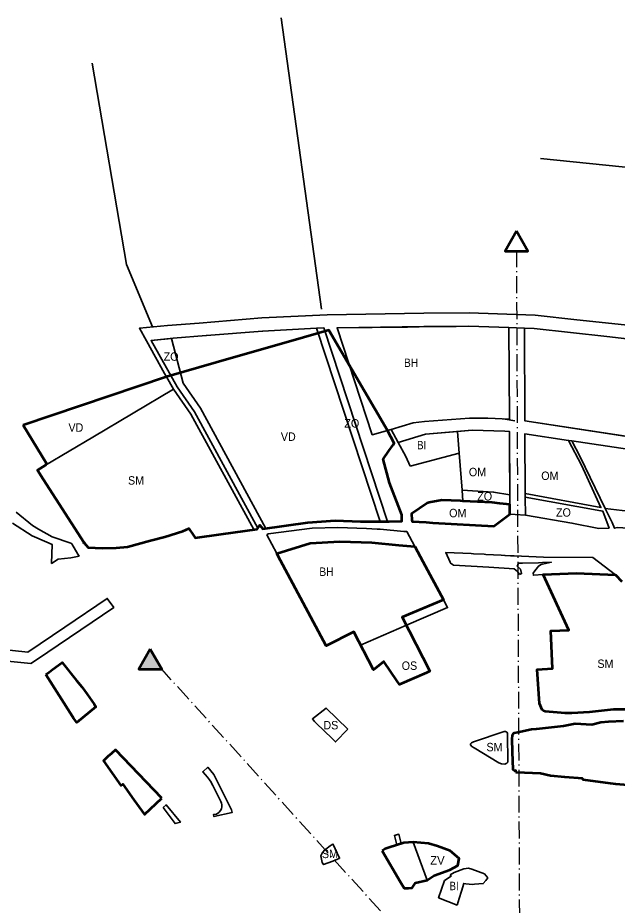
# Model space of a CAD drawing. Extents: x -650276 to -642489, y -1074311 to -1066658.
# Drawn here: x -647782 to -646929, y -1070373 to -1069110 of the extents above; entities that cross this region are included whole.
import ezdxf

# ---------------------------------------------------------------- set-up
doc = ezdxf.new("R2010")
doc.units = 0
doc.header["$LTSCALE"] = 4.8
doc.header["$PDMODE"] = 32
doc.header["$PDSIZE"] = 2.4
doc.linetypes.add('DOT_DASHED', pattern=[7.7, 5, -1.2, 0.3, -1.2])
for name, color, linetype, lineweight in [('1', 7, 'Continuous', 35), ('12', 7, 'Continuous', 35), ('15', 7, 'Continuous', 35), ('18', 7, 'Continuous', 35), ('2', 7, 'Continuous', 35), ('24', 7, 'Continuous', 35), ('35', 7, 'Continuous', 35), ('40', 7, 'Continuous', 35), ('42', 7, 'Continuous', 35), ('54', 7, 'Continuous', 35), ('55', 7, 'Continuous', 53), ('60', 7, 'Continuous', 53), ('9', 7, 'Continuous', 35)]:
    doc.layers.add(name, color=color, linetype=linetype, lineweight=lineweight)
doc.layers.add('62', color=7, linetype='Continuous')

msp = doc.modelspace()

# ---------------------------------------------------------------- hatches: boundary and pattern name
at = {"layer": '55'}
msp.add_hatch(color=256, dxfattribs=at).paths.add_polyline_path([(-647593.545, -1070008.59), (-647609.496, -1070037.236), (-647577.112, -1070037.236)])

# ---------------------------------------------------------------- linework, layer by layer
at = {"layer": '1'}
for points in [[(-647251.002, -1069695.852), (-647219.628, -1069686.746), (-647203.374, -1069684.716), (-647139.649, -1069679.961), (-647113.255, -1069679.966), (-647082.761, -1069681.399), (-647083.356, -1069551.018), (-647140.247, -1069549.071), (-647158.572, -1069549.252), (-647211.05, -1069549.77), (-647227.623, -1069550.23), (-647327.682, -1069551.263), (-647277.71, -1069703.421)], [(-646944.168, -1069563.743), (-647047.648, -1069552.245), (-647061.304, -1069551.773), (-647060.7, -1069683.894), (-646863, -1069714), (-646846, -1069575)], [(-647365.866, -1069857.774), (-647413.461, -1069872.442), (-647343.28, -1070003.81), (-647339.69, -1070001.95), (-647330.5, -1069997.19), (-647304.05, -1069983.79), (-647294.257, -1070002.745), (-647229.096, -1069974.658), (-647235, -1069963), (-647176.499, -1069938.333), (-647205.781, -1069883.796), (-647217.177, -1069862.57), (-647243.231, -1069860.34), (-647278.525, -1069857.002), (-647323.794, -1069855.468)]]:
    msp.add_lwpolyline(points, close=True, dxfattribs=at)
at = {"layer": '12'}
for points in [[(-647150.138, -1069782.334), (-647105.334, -1069785.168), (-647082.271, -1069788.81), (-647082.682, -1069698.791), (-647089.456, -1069698.579), (-647135.585, -1069697.137), (-647156.782, -1069698.901), (-647154.33, -1069729.69)], [(-647060.23, -1069786.932), (-646952.56, -1069807.13), (-646980.4, -1069746.98), (-646998.56, -1069711.443), (-647060.617, -1069702.116)]]:
    msp.add_lwpolyline(points, close=True, dxfattribs=at)
for points in [[(-647107.04, -1069799.84), (-647148.9, -1069797.88), (-647148.9, -1069797.88), (-647178.73, -1069796.4), (-647196.616, -1069800.068)], [(-647196.616, -1069800.068), (-647199.65, -1069800.69), (-647221.87, -1069816.21), (-647221.28, -1069824.74), (-647221.14, -1069826.761), (-647191.66, -1069828.58), (-647201.106, -1069827.997), (-647191.66, -1069828.58), (-647104.741, -1069833.568)], [(-647082.206, -1069802.916), (-647107.04, -1069799.84), (-647107.04, -1069799.84)], [(-647104.741, -1069833.568), (-647082.145, -1069816.321), (-647082.206, -1069802.916)]]:
    msp.add_lwpolyline(points, dxfattribs=at)
at = {"layer": '15'}
for points in [[(-646910.029, -1069548.006), (-646986.633, -1069539.757), (-647046.325, -1069533.275), (-647140.008, -1069530.068), (-647204.293, -1069530.647), (-647341.697, -1069532.602), (-647434.969, -1069537.141), (-647523.931, -1069544.499), (-647568.792, -1069548.21), (-647608.81, -1069551.868), (-647598.735, -1069570.026), (-647573.15, -1069616.16), (-647570.37, -1069621.18), (-647560.36, -1069638.39), (-647535.588, -1069674.163), (-647446.322, -1069838.338), (-647441.19, -1069837.6), (-647440.46, -1069836.558), (-647530.471, -1069671.013), (-647555.266, -1069635.207), (-647592.199, -1069569.411), (-647560.836, -1069566.036), (-647514.067, -1069562.282), (-647513.66, -1069562.249), (-647433.779, -1069556.106), (-647433.779, -1069556.106), (-647356.899, -1069552.034), (-647346.554, -1069551.486), (-647256.034, -1069827.107), (-647235.49, -1069826.51), (-647235.62, -1069817.62), (-647253.45, -1069771.95), (-647262.46, -1069738.25), (-647259.11, -1069733.52), (-647253.97, -1069726.27), (-647246.42, -1069715.63), (-647249.555, -1069709.677), (-647256.061, -1069697.32), (-647277.71, -1069703.421), (-647327.682, -1069551.263), (-647204.208, -1069549.647), (-647140.247, -1069549.071), (-647083.356, -1069551.018), (-647061.304, -1069551.773), (-647047.702, -1069552.239), (-646944.167, -1069563.743), (-646822.169, -1069577.72)], [(-647083.356, -1069551.018), (-647082.761, -1069681.399), (-647113.255, -1069679.966), (-647139.649, -1069679.961), (-647203.374, -1069684.716), (-647219.628, -1069686.746), (-647251.002, -1069695.852), (-647240.994, -1069714.513), (-647202.181, -1069702.678), (-647135.585, -1069697.137), (-647089.456, -1069698.579), (-647082.682, -1069698.791), (-647082.145, -1069816.321)], [(-647060.617, -1069702.116), (-646998.56, -1069711.443), (-646993.771, -1069712.163), (-646775.286, -1069745.022), (-646734.48, -1069751.35), (-646732.143, -1069733.308), (-646772.906, -1069727.176), (-646842.148, -1069716.763), (-647060.7, -1069683.894), (-647061.304, -1069551.773), (-647083.356, -1069551.018)], [(-647082.145, -1069816.321), (-647082.145, -1069816.321), (-647074.72, -1069816.8), (-647060.029, -1069817.854), (-647060.206, -1069792.294), (-647060.23, -1069786.932), (-647060.617, -1069702.116)], [(-647082.206, -1069802.916), (-647107.04, -1069799.84), (-647148.9, -1069797.88), (-647148.9, -1069797.88), (-647178.73, -1069796.4), (-647196.616, -1069800.068)], [(-647196.616, -1069800.068), (-647199.65, -1069800.69), (-647221.87, -1069816.21), (-647221.28, -1069824.74), (-647221.14, -1069826.761), (-647205.603, -1069827.72), (-647191.66, -1069828.58), (-647201.106, -1069827.997), (-647191.66, -1069828.58), (-647104.741, -1069833.568)], [(-647104.741, -1069833.568), (-647082.145, -1069816.321), (-647082.206, -1069802.916)], [(-646931.67, -1069902.89), (-646964.111, -1069878.315), (-647034.195, -1069877.629), (-647076, -1069875.85), (-647081.25, -1069875.56), (-647081.26, -1069875.76), (-647088.94, -1069875.34), (-647088.93, -1069875.14), (-647094.24, -1069874.85), (-647116.31, -1069873.65), (-647118.77, -1069873.51), (-647133.58, -1069872.73), (-647136.94, -1069872.55), (-647173.23, -1069871.09), (-647167.14, -1069884.85)], [(-647167.14, -1069884.85), (-647166.8, -1069885.63), (-647163.55, -1069887.98), (-647162.03, -1069888.89), (-647111.76, -1069891.77)], [(-647068.2, -1069902.28), (-647065.47, -1069901.09), (-647067.02, -1069894.68), (-647071.73, -1069890.39), (-647070.87, -1069888.71), (-647069.57, -1069886.35), (-647064.32, -1069886.23), (-647041.25, -1069885.62), (-647035.6, -1069885.43), (-647023.04, -1069885), (-647035.53, -1069887.44), (-647037.79, -1069887.88), (-647041.47, -1069890.42), (-647042.75, -1069892.14), (-647046.49, -1069897.19), (-647048.8, -1069900.51), (-647048.67, -1069903.32), (-647034.51, -1069902.21)], [(-647111.76, -1069891.77), (-647075.97, -1069894.33), (-647071, -1069897.87), (-647068.2, -1069902.28)], [(-647034.51, -1069902.21), (-647032.16, -1069902.13), (-646987.56, -1069900.52), (-646931.67, -1069902.89)]]:
    msp.add_lwpolyline(points, dxfattribs=at)
for points in [[(-647217.177, -1069862.57), (-647228.77, -1069840.98), (-647232.66, -1069841.07), (-647266.62, -1069837.86), (-647270.71, -1069837.61), (-647285.9, -1069836.66), (-647326.71, -1069835.46), (-647363.21, -1069836.64), (-647425.73, -1069844.31), (-647427.62, -1069845.94), (-647413.461, -1069872.442), (-647365.866, -1069857.774), (-647323.794, -1069855.468), (-647278.525, -1069857.002), (-647239.912, -1069860.654)], [(-647815.788, -1070007.72), (-647767.622, -1070012.66), (-647714.989, -1069977.087), (-647654.577, -1069936.255), (-647645.274, -1069949.279), (-647755.356, -1070023.682), (-647763.476, -1070029.17), (-647820.515, -1070023.319), (-647818.81, -1070016.41)], [(-647235, -1069963), (-647176.499, -1069938.333), (-647170.546, -1069949.42), (-647229.096, -1069974.658)], [(-647493.13, -1070225.217), (-647492.138, -1070227.681), (-647491.692, -1070229.974), (-647491.767, -1070233.217), (-647492.286, -1070235.393), (-647493.254, -1070237.6), (-647495.889, -1070240.926), (-647499.448, -1070243.223), (-647503.6, -1070243.95), (-647502.82, -1070246.91), (-647476.94, -1070240.79), (-647477.78, -1070237.42), (-647484.35, -1070223.91), (-647491.97, -1070208.95), (-647499.68, -1070193.54), (-647502.99, -1070186.94), (-647511.73, -1070176.61), (-647518.813, -1070183.069), (-647512.222, -1070190.785), (-647509.223, -1070194.61), (-647507.054, -1070197.854), (-647505.688, -1070200.172), (-647504.419, -1070202.575)], [(-647575.15, -1070233.71), (-647570.887, -1070229.877), (-647550.603, -1070254.911), (-647558.19, -1070256.86)], [(-647575.15, -1070233.71), (-647558.19, -1070256.86), (-647550.603, -1070254.911), (-647570.887, -1070229.877)], [(-647242.698, -1070287.238), (-647236.567, -1070285.154), (-647239.781, -1070272.031), (-647242.06, -1070272.35), (-647246.28, -1070273.733)]]:
    msp.add_lwpolyline(points, close=True, dxfattribs=at)
at = {"layer": '18'}
for points in [[(-647560.36, -1069638.39), (-647674.901, -1069706.701), (-647742.36, -1069746.93)], [(-647446.322, -1069838.338), (-647535.588, -1069674.163), (-647560.36, -1069638.39)], [(-647742.36, -1069746.93), (-647752.32, -1069752.95), (-647753.7, -1069753.9)], [(-647753.7, -1069753.9), (-647751.66, -1069757.12), (-647745.84, -1069766.71), (-647737.17, -1069780.85), (-647700.58, -1069837.2), (-647687.45, -1069857.15), (-647681.51, -1069863.72)], [(-647641.78, -1069864.26), (-647625.83, -1069863.19), (-647593.07, -1069853.74), (-647583.62, -1069851.13), (-647572.63, -1069848.63), (-647559.47, -1069844.92), (-647547.12, -1069840.87), (-647538.34, -1069836.68), (-647536.82, -1069838.87), (-647531.33, -1069847.23), (-647529.5, -1069849.99), (-647500.03, -1069846.28), (-647492.76, -1069845.02), (-647446.322, -1069838.338)], [(-647681.51, -1069863.72), (-647661.79, -1069864.92), (-647641.78, -1069864.26)], [(-646922.79, -1069912.31), (-646931.67, -1069902.89), (-646987.56, -1069900.52), (-647032.16, -1069902.13), (-647034.51, -1069902.21), (-646998.06, -1069981.49), (-647024.05, -1069982.48), (-647021.27, -1070036.28), (-647043.25, -1070037.29), (-647040.12, -1070086.11), (-647036.03, -1070094.96), (-647034.17, -1070096.49), (-647031.73, -1070097.21), (-647003.49, -1070099.66), (-646993.92, -1070099.49), (-646968.89, -1070098.02), (-646934.63, -1070094.24), (-646904.97, -1070094.52)]]:
    msp.add_lwpolyline(points, dxfattribs=at)
for points in [[(-646785.437, -1069827.534), (-646775.286, -1069745.022), (-646993.771, -1069712.163), (-646981.92, -1069734.86), (-646946.369, -1069808.291)], [(-647097.63, -1070170.37), (-647093.89, -1070171.55), (-647089.47, -1070172.21), (-647086.62, -1070170.89), (-647084.98, -1070169.29), (-647085.17, -1070154.78), (-647085.24, -1070144.07), (-647085.62, -1070128.24), (-647086.49, -1070126.62), (-647088.08, -1070125.63), (-647090.2, -1070125.64), (-647133.96, -1070140.44), (-647136.65, -1070141.75), (-647137.99, -1070143.09), (-647137.96, -1070144.66), (-647136.09, -1070146.97), (-647132.95, -1070149.08)], [(-647333.87, -1070285.66), (-647324.11, -1070306.21), (-647324.94, -1070306.63), (-647327.18, -1070307.52), (-647333.97, -1070310.22), (-647346.97, -1070315.05), (-647349, -1070312), (-647350.67, -1070302.55), (-647348.677, -1070297.894), (-647345.27, -1070293.99), (-647343.9, -1070292.96), (-647337.56, -1070288.43), (-647334.91, -1070286.51)]]:
    msp.add_lwpolyline(points, close=True, dxfattribs=at)
msp.add_point((-647687.45, -1069857.15), dxfattribs=at)
at = {"layer": '2'}
msp.add_lwpolyline([(-647223.66, -1069748.26), (-647154.33, -1069729.69), (-647156.782, -1069698.901), (-647202.181, -1069702.678), (-647240.994, -1069714.513), (-647230.16, -1069734.42)], close=True, dxfattribs=at)
for points in [[(-647167.03, -1070329.81), (-647165.36, -1070331.59), (-647174.81, -1070338.01), (-647183.55, -1070362.35), (-647156.9, -1070372.69)], [(-647113.37, -1070333.96), (-647118.28, -1070328.29), (-647135.94, -1070321.54), (-647140.83, -1070320.47), (-647147.66, -1070321.04), (-647161.17, -1070326.29), (-647167.03, -1070329.81)], [(-647156.9, -1070372.69), (-647154.31, -1070363.46), (-647151.09, -1070353.15), (-647147.6, -1070341.95), (-647144.57, -1070342.42), (-647139.84, -1070343.16), (-647135.62, -1070343.32), (-647132.49, -1070342.91)], [(-647132.49, -1070342.91), (-647119.88, -1070342.1), (-647116.03, -1070337.68), (-647113.37, -1070333.96)]]:
    msp.add_lwpolyline(points, dxfattribs=at)
at = {"layer": '24'}
msp.add_lwpolyline([(-647312.485, -1070122.583), (-647329.932, -1070140.465), (-647334.81, -1070135.73), (-647357.4, -1070113.69), (-647359.8, -1070111.34), (-647362.87, -1070107.74), (-647343.454, -1070092.368)], close=True, dxfattribs=at)
at = {"layer": '35'}
for points in [[(-647356.899, -1069552.034), (-647433.779, -1069556.106), (-647433.779, -1069556.106), (-647513.66, -1069562.249), (-647514.067, -1069562.282), (-647560.836, -1069566.036), (-647563.104, -1069566.28)], [(-647369.3, -1069828.22), (-647330.46, -1069825.51), (-647294.38, -1069826.88), (-647270.09, -1069827.02), (-647266.581, -1069827.042), (-647356.899, -1069552.034)], [(-647563.104, -1069566.28), (-647546.777, -1069629.901), (-647521.943, -1069665.763)], [(-647521.943, -1069665.763), (-647428.993, -1069836.714), (-647369.3, -1069828.22)]]:
    msp.add_lwpolyline(points, dxfattribs=at)
msp.add_lwpolyline([(-647740.74, -1069744.24), (-647742.36, -1069746.93), (-647674.901, -1069706.701), (-647560.36, -1069638.39), (-647570.37, -1069621.18), (-647701.61, -1069665.279), (-647774.11, -1069689.64)], close=True, dxfattribs=at)
at = {"layer": '40'}
msp.add_lwpolyline([(-647199.79, -1070337.21), (-647189.63, -1070330.53), (-647167.43, -1070322.66), (-647155.89, -1070316.51), (-647154.23, -1070306.63), (-647167.15, -1070295.69), (-647184.77, -1070288.73), (-647197.68, -1070285.3), (-647219.36, -1070283.36)], close=True, dxfattribs=at)
at = {"layer": '42'}
msp.add_line((-647266.581, -1069827.042), (-647256.034, -1069827.107), dxfattribs=at)
for points in [[(-647256.034, -1069827.107), (-647346.554, -1069551.486), (-647356.899, -1069552.034), (-647266.581, -1069827.042)], [(-647082.271, -1069788.81), (-647105.334, -1069785.168), (-647105.334, -1069785.168), (-647150.138, -1069782.334), (-647148.9, -1069797.88), (-647107.04, -1069799.84)], [(-647107.04, -1069799.84), (-647082.206, -1069802.916), (-647082.271, -1069788.81)], [(-647789.55, -1069829.12), (-647761.54, -1069847.24), (-647740.46, -1069856.29), (-647733.06, -1069859.46), (-647733.71, -1069886.65), (-647724.35, -1069880.48), (-647706.39, -1069878.81), (-647694.63, -1069876.07), (-647696.25, -1069873.35), (-647704.99, -1069858.7), (-647706.44, -1069857.98), (-647732.93, -1069848.5), (-647752.25, -1069837.95), (-647760.79, -1069832.61), (-647783.96, -1069813.49)]]:
    msp.add_lwpolyline(points, dxfattribs=at)
for points in [[(-647555.266, -1069635.207), (-647530.471, -1069671.013), (-647440.46, -1069836.558), (-647437.46, -1069832.27), (-647433.32, -1069837.33), (-647428.993, -1069836.714), (-647521.943, -1069665.763), (-647546.777, -1069629.901), (-647563.104, -1069566.28), (-647592.199, -1069569.411)], [(-646775.286, -1069745.022), (-646785.437, -1069827.534), (-646946.369, -1069808.291), (-646936.6, -1069828.47), (-646933.39, -1069836.51), (-646929.67, -1069835.68), (-646826.63, -1069841.84), (-646778.74, -1069850.44), (-646751.8, -1069853.72), (-646743.31, -1069854.26), (-646743.7, -1069850.07), (-646745.56, -1069829.84), (-646743.85, -1069817.72), (-646734.48, -1069751.35)], [(-646993.81, -1069829.12), (-646993.81, -1069829.12), (-646955.45, -1069836.93), (-646940.94, -1069836.34), (-646950.08, -1069812.16), (-646952.68, -1069811.69), (-647060.206, -1069792.294), (-647060.029, -1069817.854)]]:
    msp.add_lwpolyline(points, close=True, dxfattribs=at)
at = {"layer": '54'}
for p, q in [((-647407.408, -1069110.064), (-647349.831, -1069524.717)), ((-646340.757, -1069381.428), (-647038.68, -1069310.312)), ((-647091.408, -1069680.918), (-647074.799, -1069683.763))]:
    msp.add_line(p, q, dxfattribs=at)
msp.add_lwpolyline([(-647675.801, -1069174.849), (-647627, -1069461), (-647590.168, -1069549.978)], dxfattribs=at)
at = {"layer": '55', "linetype": 'DOT_DASHED', "lineweight": 25}
for p, q in [((-647072.859, -1069440.93), (-647067.564, -1070600.224)), ((-647067.564, -1070600.224), (-647577.112, -1070037.236))]:
    msp.add_line(p, q, dxfattribs=at)
at = {"layer": '55'}
for points in [[(-647072.884, -1069413.607), (-647088.835, -1069442.253), (-647056.451, -1069442.253)], [(-647593.545, -1070008.59), (-647609.496, -1070037.236), (-647577.112, -1070037.236)]]:
    msp.add_lwpolyline(points, close=True, dxfattribs=at)
at = {"layer": '60'}
for points in [[(-647774.11, -1069689.64), (-647740.74, -1069744.24), (-647742.36, -1069746.93), (-647753.7, -1069753.9), (-647745.84, -1069766.71), (-647687.45, -1069857.15), (-647681.51, -1069863.72), (-647661.79, -1069864.92), (-647641.78, -1069864.26), (-647625.83, -1069863.19), (-647593.07, -1069853.74), (-647572.63, -1069848.63), (-647547.12, -1069840.87), (-647538.34, -1069836.68), (-647531.33, -1069847.23), (-647529.5, -1069849.99), (-647492.76, -1069845.02), (-647441.19, -1069837.6), (-647437.46, -1069832.27), (-647433.32, -1069837.33), (-647369.3, -1069828.22), (-647330.46, -1069825.51), (-647294.38, -1069826.88), (-647270.09, -1069827.02), (-647253.88, -1069827.12), (-647236.5, -1069826.63), (-647235.49, -1069826.51), (-647235.62, -1069817.62), (-647253.45, -1069771.95), (-647262.46, -1069738.25), (-647253.97, -1069726.27), (-647247.86, -1069717.66), (-647246.42, -1069715.63), (-647256.061, -1069697.32), (-647339.58, -1069554.46), (-647375.71, -1069564.91), (-647499.63, -1069600.73), (-647570.37, -1069621.18)], [(-647196.616, -1069800.068), (-647199.65, -1069800.69), (-647221.87, -1069816.21), (-647221.28, -1069824.74), (-647221.14, -1069826.761), (-647201.106, -1069827.997), (-647191.66, -1069828.58), (-647104.741, -1069833.568), (-647082.145, -1069816.321), (-647082.206, -1069802.916), (-647096.39, -1069801.15), (-647107.04, -1069799.84), (-647148.9, -1069797.88), (-647152.39, -1069797.7), (-647178.73, -1069796.4)], [(-647408.115, -1069882.449), (-647413.461, -1069872.442), (-647365.866, -1069857.774), (-647323.794, -1069855.468), (-647278.525, -1069857.002), (-647239.912, -1069860.654), (-647217.177, -1069862.57), (-647205.781, -1069883.796), (-647176.499, -1069938.333), (-647235, -1069963), (-647195.933, -1070040.107), (-647200.796, -1070042.246), (-647238.99, -1070059.05), (-647238.99, -1070059.05), (-647242.362, -1070054.067), (-647261.27, -1070026.12), (-647276, -1070038.08), (-647304.05, -1069983.79), (-647343.28, -1070003.81), (-647397.738, -1069901.873)], [(-647741.98, -1070044.74), (-647737.34, -1070041.32), (-647732.47, -1070037.73), (-647718.564, -1070027.479), (-647698.172, -1070052.962), (-647690.674, -1070062.331), (-647683.145, -1070072.735), (-647673.357, -1070086.635), (-647670.687, -1070090.426), (-647697.889, -1070112.941), (-647702.57, -1070106.56), (-647704.02, -1070104.5)], [(-647576.812, -1070220.636), (-647642.855, -1070151.617), (-647648.73, -1070157.05), (-647653.52, -1070161.48), (-647659.831, -1070167.317), (-647635.1, -1070202.5), (-647632.56, -1070200.72), (-647616.6, -1070223), (-647601.726, -1070243.764)], [(-647263.72, -1070295.43), (-647237.57, -1070340.12), (-647232.55, -1070348.65), (-647226.24, -1070348.88), (-647220.9, -1070348.04), (-647216.16, -1070340.99), (-647199.79, -1070337.21), (-647189.63, -1070330.53), (-647167.43, -1070322.66), (-647155.89, -1070316.51), (-647154.23, -1070306.63), (-647167.15, -1070295.69), (-647184.77, -1070288.73), (-647197.68, -1070285.3), (-647219.36, -1070283.36), (-647232.87, -1070284.15), (-647253.53, -1070290.92), (-647259.22, -1070292.91)]]:
    msp.add_lwpolyline(points, close=True, dxfattribs=at)
for points in [[(-646904.97, -1070094.52), (-646934.63, -1070094.24), (-646968.89, -1070098.02), (-646993.92, -1070099.49), (-647003.49, -1070099.66), (-647031.73, -1070097.21), (-647034.17, -1070096.49), (-647036.03, -1070094.96), (-647040.12, -1070086.11), (-647043.25, -1070037.29), (-647021.27, -1070036.28), (-647024.05, -1069982.48), (-646998.06, -1069981.49), (-647034.51, -1069902.21), (-646987.56, -1069900.52), (-646931.67, -1069902.89), (-646922.79, -1069912.31)], [(-646874.04, -1070205.5), (-646931.25, -1070200.56), (-646938.98, -1070199.89), (-646977.7, -1070194.45), (-646977.7, -1070193.62), (-646978.72, -1070193.6), (-646978.73, -1070192.54), (-647003.89, -1070190.89), (-647024.2, -1070188.68), (-647038.31, -1070185.73), (-647061.2, -1070184.6), (-647073.35, -1070184.01), (-647073.42, -1070181.47), (-647075.42, -1070181.53), (-647076.83, -1070180.73), (-647077.39, -1070179.57), (-647078.23, -1070155.29), (-647078.72, -1070135.49), (-647078.54, -1070132.1), (-647078.05, -1070129.8), (-647076.99, -1070128.48), (-647075.81, -1070127.72), (-647070.7, -1070126.64), (-647051.14, -1070122.49), (-647044.19, -1070121.78), (-647005.97, -1070117.89), (-646989.24, -1070114.17), (-646989.24, -1070114.17), (-646965.6, -1070115.74), (-646952.66, -1070112.57), (-646941.99, -1070111.74), (-646920.68, -1070110.58)]]:
    msp.add_lwpolyline(points, dxfattribs=at)
at = {"layer": '9'}
msp.add_lwpolyline([(-647261.27, -1070026.12), (-647238.99, -1070059.05), (-647195.933, -1070040.107), (-647229.096, -1069974.658), (-647294.257, -1070002.745), (-647276, -1070038.08)], close=True, dxfattribs=at)

# ---------------------------------------------------------------- texts
at = {"layer": '62'}
for s, width, p in [('ZO', 0.95, (-647574.423, -1069598.188)), ('BH', 0.9, (-647232.617, -1069607.053)), ('ZO', 0.95, (-647317.423, -1069693.188)), ('VD', 0.95, (-647709.767, -1069699.204)), ('VD', 0.95, (-647407.767, -1069712.204)), ('BI', 0.85, (-647213.92, -1069724.163)), ('OM', 0.95, (-647140.377, -1069762.527)), ('OM', 0.95, (-647037.483, -1069767.845)), ('SM', 0.95, (-647625.077, -1069774.464)), ('ZO', 0.95, (-647128.473, -1069797.058)), ('OM', 0.95, (-647168.433, -1069820.895)), ('ZO', 0.95, (-647016.473, -1069820.058)), ('BH', 0.9, (-647352.947, -1069904.358)), ('OS', 0.95, (-647235.865, -1070038.102)), ('SM', 0.95, (-646957.615, -1070035.352)), ('DS', 0.95, (-647347.216, -1070122.778)), ('SM', 0.95, (-647115.357, -1070153.941)), ('SM', 0.95, (-647349.357, -1070305.941)), ('BI', 0.85, (-647167.828, -1070351.569))]:
    msp.add_text(s, height=12, dxfattribs=dict(at, width=width)).set_placement(p)
msp.add_text('ZV', height=12, dxfattribs=at).set_placement((-647195.386, -1070315.148))

doc.saveas('drawing.dxf')
